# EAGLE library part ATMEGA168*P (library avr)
MICROCONTROLLER 16 kBytes FLASH 1 kBytes SRAM 512 Bytes EEPROM USART 8-channel 10 bit ADC
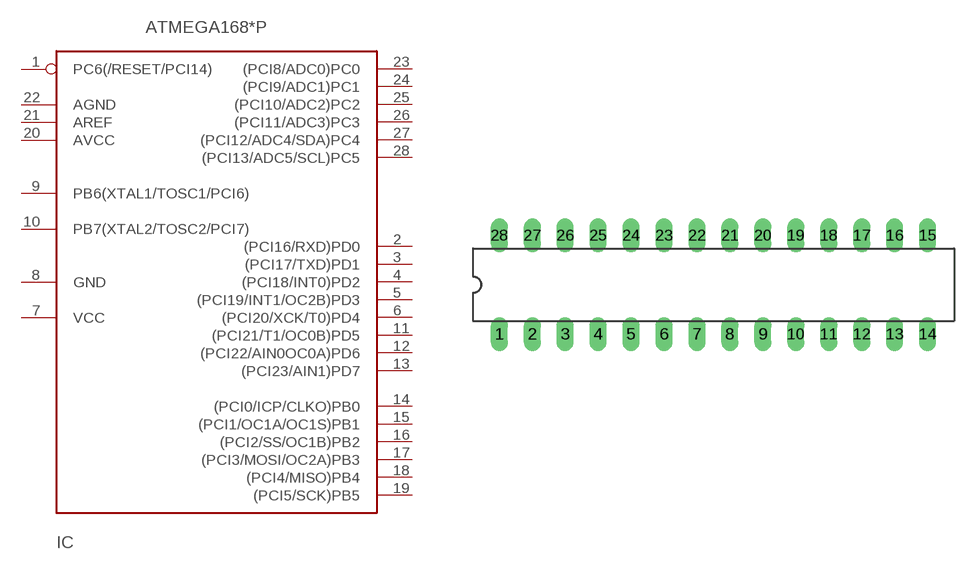
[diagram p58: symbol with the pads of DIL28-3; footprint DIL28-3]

Designator prefix IC

## ATMEGA168-20P, ATMEGA168V-10P  [DIL28-3]
1  PC6(/RESET/PCI14)
2  (PCI16/RXD)PD0
3  (PCI17/TXD)PD1
4  (PCI18/INT0)PD2
5  (PCI19/INT1/OC2B)PD3
6  (PCI20/XCK/T0)PD4
7  VCC
8  GND
9  PB6(XTAL1/TOSC1/PCI6)
10  PB7(XTAL2/TOSC2/PCI7)
11  (PCI21/T1/OC0B)PD5
12  (PCI22/AIN0OC0A)PD6
13  (PCI23/AIN1)PD7
14  (PCI0/ICP/CLKO)PB0
15  (PCI1/OC1A/OC1S)PB1
16  (PCI2/SS/OC1B)PB2
17  (PCI3/MOSI/OC2A)PB3
18  (PCI4/MISO)PB4
19  (PCI5/SCK)PB5
20  AVCC
21  AREF
22  AGND
23  (PCI8/ADC0)PC0
24  (PCI9/ADC1)PC1
25  (PCI10/ADC2)PC2
26  (PCI11/ADC3)PC3
27  (PCI12/ADC4/SDA)PC4
28  (PCI13/ADC5/SCL)PC5

## Footprint DIL28-3 (pad centres in mm)
Dual In Line 0.3 inch
drill 0.813 long: 1 -16.51,-3.81; 2 -13.97,-3.81; 3 -11.43,-3.81; 4 -8.89,-3.81; 5 -6.35,-3.81; 6 -3.81,-3.81; 7 -1.27,-3.81; 8 1.27,-3.81; 9 3.81,-3.81; 10 6.35,-3.81; 11 8.89,-3.81; 12 11.43,-3.81; 13 13.97,-3.81; 14 16.51,-3.81; 15 16.51,3.81; 16 13.97,3.81; 17 11.43,3.81; 18 8.89,3.81; 19 6.35,3.81; 20 3.81,3.81; 21 1.27,3.81; 22 -1.27,3.81; 23 -3.81,3.81; 24 -6.35,3.81; 25 -8.89,3.81; 26 -11.43,3.81; 27 -13.97,3.81; 28 -16.51,3.81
